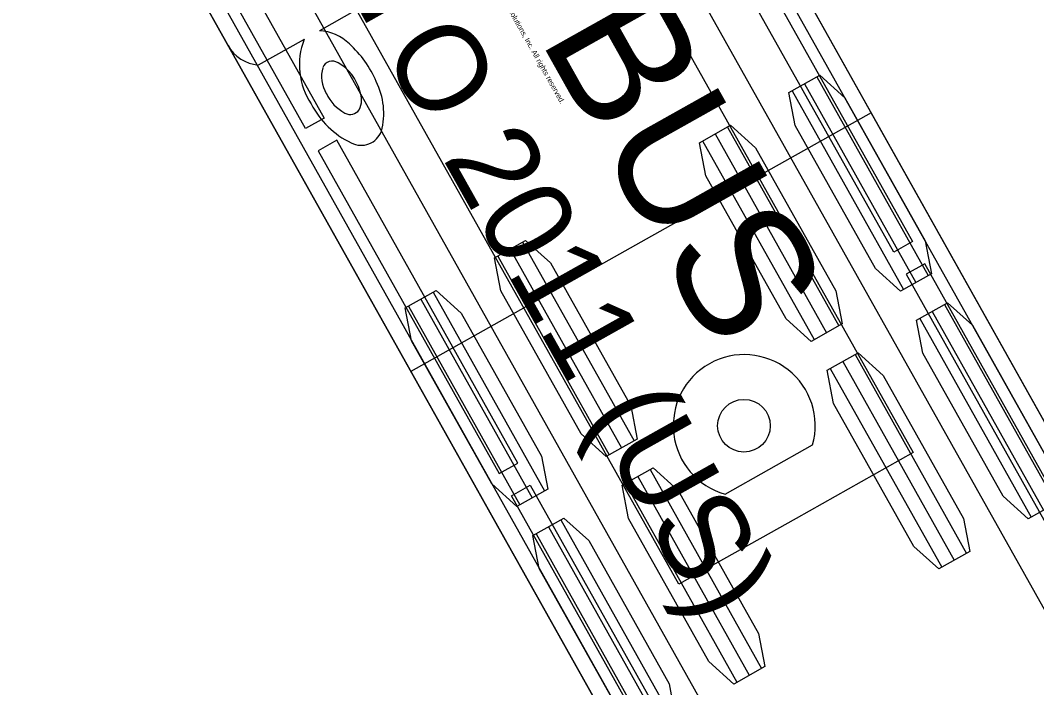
# Model space of a CAD drawing. Extents: x 1639988 to 1641860, y 841974 to 844187.
# Drawn here: x 1640597 to 1640613.36, y 843356.33 to 843367.07 of the extents above; entities that cross this region are included whole.
import ezdxf

# ---------------------------------------------------------------- set-up
doc = ezdxf.new("R2010")
doc.units = 0
for name, color, linetype in [('Scratch_Level_1', 7, 'Continuous'), ('Scratch_Level_2', 7, 'Continuous'), ('Scratch_Level_3', 7, 'Continuous'), ('Scratch_Level_4', 7, 'Continuous'), ('Scratch_Level_5', 7, 'Continuous'), ('Scratch_Level_6', 7, 'Continuous')]:
    doc.layers.add(name, color=color, linetype=linetype)

msp = doc.modelspace()

# ---------------------------------------------------------------- linework, layer by layer
at = {"layer": 'Scratch_Level_1'}
for p, q in [((1640609.821, 843366.155), (1640611.615, 843362.958)), ((1640609.621, 843366.043), (1640611.415, 843362.845)), ((1640609.421, 843365.931), (1640611.215, 843362.733)), ((1640608.382, 843365.348), (1640610.176, 843362.15)), ((1640608.182, 843365.236), (1640609.976, 843362.038)), ((1640607.982, 843365.124), (1640609.776, 843361.926)), ((1640605.082, 843363.497), (1640606.877, 843360.299)), ((1640604.883, 843363.384), (1640606.677, 843360.187)), ((1640604.683, 843363.272), (1640606.477, 843360.075)), ((1640603.643, 843362.689), (1640605.438, 843359.491)), ((1640603.444, 843362.577), (1640605.238, 843359.379)), ((1640603.244, 843362.465), (1640605.038, 843359.267)), ((1640611.676, 843362.38), (1640613.47, 843359.183)), ((1640611.876, 843362.493), (1640613.67, 843359.295)), ((1640611.476, 843362.268), (1640613.271, 843359.071)), ((1640610.237, 843361.573), (1640612.031, 843358.375)), ((1640610.437, 843361.685), (1640612.231, 843358.487)), ((1640610.037, 843361.461), (1640611.832, 843358.263)), ((1640608.343, 843359.442), (1640609.753, 843360.233)), ((1640607.138, 843359.834), (1640608.932, 843356.636)), ((1640606.738, 843359.609), (1640608.532, 843356.412)), ((1640606.938, 843359.722), (1640608.732, 843356.524)), ((1640605.499, 843358.914), (1640607.293, 843355.717)), ((1640605.699, 843359.026), (1640607.493, 843355.829)), ((1640605.299, 843358.802), (1640607.093, 843355.604))]:
    msp.add_line(p, q, dxfattribs=at)
for points in [[(1640569.35, 843442.491), (1640571.641, 843437.743), (1640573.976, 843433.013), (1640576.351, 843428.298), (1640578.765, 843423.598), (1640581.214, 843418.911), (1640583.696, 843414.235), (1640586.206, 843409.569), (1640588.742, 843404.91), (1640593.874, 843395.608), (1640599.062, 843386.314), (1640636.63, 843319.355), (1640629.218, 843315.196), (1640629.14, 843315.333), (1640629.14, 843315.333)], [(1640629.14, 843315.333), (1640571.712, 843417.686), (1640569.11, 843422.364), (1640566.534, 843427.059), (1640563.994, 843431.777), (1640560.226, 843438.882)], [(1640600.34, 843366.66), (1640597.808, 843371.174), (1640597.225, 843370.382), (1640597.224, 843370.382), (1640597.232, 843370.344), (1640597.232, 843370.344), (1640597.232, 843370.343), (1640597.271, 843370.273), (1640597.272, 843370.273), (1640597.584, 843370.429), (1640597.634, 843370.339), (1640597.132, 843369.763), (1640597.131, 843369.763), (1640597.072, 843369.866), (1640597.073, 843369.869), (1640597.234, 843370.232), (1640597.234, 843370.235), (1640597.193, 843370.311)], [(1640606.785, 843369.688), (1640606.186, 843369.352), (1640606.302, 843369.144), (1640611.373, 843360.108), (1640609.485, 843359.048), (1640607.596, 843357.989), (1640602.526, 843367.025), (1640602.409, 843367.233), (1640601.811, 843366.897)], [(1640601.565, 843366.759), (1640600.828, 843366.346)], [(1640636.576, 843319.405), (1640636.595, 843319.416), (1640636.561, 843319.478), (1640633.788, 843324.42), (1640610.695, 843365.576), (1640606.989, 843363.496), (1640603.283, 843361.416), (1640626.375, 843320.261), (1640629.149, 843315.319), (1640629.184, 843315.257), (1640629.203, 843315.268)]]:
    msp.add_lwpolyline(points, dxfattribs=at)
for points in [[(1640609.371, 843365.903), (1640609.87, 843366.183), (1640610.272, 843365.82), (1640611.564, 843363.517), (1640611.665, 843362.985), (1640611.166, 843362.706), (1640610.764, 843363.069), (1640609.472, 843365.371)], [(1640607.933, 843365.096), (1640608.431, 843365.376), (1640608.833, 843365.012), (1640610.125, 843362.71), (1640610.226, 843362.178), (1640609.727, 843361.898), (1640609.325, 843362.261), (1640608.033, 843364.564)], [(1640604.633, 843363.244), (1640605.132, 843363.524), (1640605.533, 843363.161), (1640606.825, 843360.859), (1640606.926, 843360.327), (1640606.427, 843360.047), (1640606.026, 843360.41), (1640604.734, 843362.712)], [(1640603.194, 843362.437), (1640603.693, 843362.717), (1640604.094, 843362.354), (1640605.386, 843360.051), (1640605.487, 843359.519), (1640604.988, 843359.239), (1640604.587, 843359.603), (1640603.295, 843361.905)], [(1640611.427, 843362.24), (1640611.926, 843362.52), (1640612.327, 843362.157), (1640613.619, 843359.855), (1640613.72, 843359.323), (1640613.221, 843359.043), (1640612.819, 843359.406), (1640611.528, 843361.708)], [(1640609.988, 843361.433), (1640610.487, 843361.713), (1640610.888, 843361.35), (1640612.18, 843359.047), (1640612.281, 843358.515), (1640611.782, 843358.235), (1640611.381, 843358.599), (1640610.089, 843360.901)], [(1640606.688, 843359.582), (1640607.187, 843359.862), (1640607.589, 843359.498), (1640608.881, 843357.196), (1640608.981, 843356.664), (1640608.483, 843356.384), (1640608.081, 843356.747), (1640606.789, 843359.05)], [(1640605.249, 843358.774), (1640605.748, 843359.054), (1640606.15, 843358.691), (1640607.442, 843356.388), (1640607.542, 843355.856), (1640607.044, 843355.577), (1640606.642, 843355.94), (1640605.35, 843358.242)]]:
    msp.add_lwpolyline(points, close=True, dxfattribs=at)
msp.add_circle((1640608.647, 843360.541), 0.424, dxfattribs=at)
for centre, radius, start, end in [((1640601.78, 843366.169), 0.729, 45.1057, 87.6197), ((1640600.88, 843366.963), 0.619, 209.2952, 265.1369), ((1640602.625, 843366.351), 1.136, 158.9272, 213.7185), ((1640601.135, 843365.401), 1.73, 23.1239, 47.9224), ((1640602.368, 843366.162), 0.522, 164.3026, 211.4667), ((1640602.021, 843366.24), 0.169, 57.7316, 157.8503), ((1640601.753, 843365.745), 0.732, 14.4711, 60.7055), ((1640601.711, 843365.572), 1.136, 345.0612, 26.5819), ((1640602.529, 843366.162), 0.664, 204.2011, 242.4228), ((1640602.128, 843365.788), 0.362, 333.5938, 22.6348), ((1640602.939, 843366.368), 1.416, 207.2254, 244.2932), ((1640602.308, 843365.721), 0.172, 239.5988, 326.7494), ((1640602.484, 843365.399), 0.346, 242.6899, 339.703), ((1640608.652, 843360.542), 1.143, 344.2972, 254.2972)]:
    msp.add_arc(centre, radius, start, end, dxfattribs=at)
at = {"layer": 'Scratch_Level_2'}
for p, q in [((1640609.821, 843366.155), (1640611.615, 843362.958)), ((1640609.621, 843366.043), (1640611.415, 843362.845)), ((1640609.421, 843365.931), (1640611.215, 843362.733)), ((1640608.382, 843365.348), (1640610.176, 843362.15)), ((1640608.182, 843365.236), (1640609.976, 843362.038)), ((1640607.982, 843365.124), (1640609.776, 843361.926)), ((1640605.082, 843363.497), (1640606.877, 843360.299)), ((1640604.883, 843363.384), (1640606.677, 843360.187)), ((1640604.683, 843363.272), (1640606.477, 843360.075)), ((1640603.643, 843362.689), (1640605.438, 843359.491)), ((1640603.444, 843362.577), (1640605.238, 843359.379)), ((1640603.244, 843362.465), (1640605.038, 843359.267)), ((1640611.676, 843362.38), (1640613.47, 843359.183)), ((1640611.876, 843362.493), (1640613.67, 843359.295)), ((1640611.476, 843362.268), (1640613.271, 843359.071)), ((1640610.237, 843361.573), (1640612.031, 843358.375)), ((1640610.437, 843361.685), (1640612.231, 843358.487)), ((1640610.037, 843361.461), (1640611.832, 843358.263)), ((1640608.343, 843359.442), (1640609.753, 843360.233)), ((1640607.138, 843359.834), (1640608.932, 843356.636)), ((1640606.738, 843359.609), (1640608.532, 843356.412)), ((1640606.938, 843359.722), (1640608.732, 843356.524)), ((1640605.499, 843358.914), (1640607.293, 843355.717)), ((1640605.699, 843359.026), (1640607.493, 843355.829)), ((1640605.299, 843358.802), (1640607.093, 843355.604))]:
    msp.add_line(p, q, dxfattribs=at)
for points in [[(1640569.35, 843442.491), (1640571.641, 843437.743), (1640573.976, 843433.013), (1640576.351, 843428.298), (1640578.765, 843423.598), (1640581.214, 843418.911), (1640583.696, 843414.235), (1640586.206, 843409.569), (1640588.742, 843404.91), (1640593.874, 843395.608), (1640599.062, 843386.314), (1640636.63, 843319.355), (1640629.218, 843315.196), (1640629.144, 843315.327), (1640629.144, 843315.327)], [(1640629.144, 843315.327), (1640571.712, 843417.686), (1640569.11, 843422.364), (1640566.534, 843427.059), (1640563.994, 843431.777), (1640560.226, 843438.882)], [(1640600.34, 843366.66), (1640597.808, 843371.174), (1640597.225, 843370.382), (1640597.224, 843370.382), (1640597.232, 843370.344), (1640597.232, 843370.344), (1640597.232, 843370.343), (1640597.271, 843370.273), (1640597.272, 843370.273), (1640597.584, 843370.429), (1640597.634, 843370.339), (1640597.132, 843369.763), (1640597.131, 843369.763), (1640597.072, 843369.866), (1640597.073, 843369.869), (1640597.234, 843370.232), (1640597.234, 843370.235), (1640597.193, 843370.311)], [(1640606.785, 843369.688), (1640606.186, 843369.352), (1640606.302, 843369.144), (1640611.373, 843360.108), (1640609.485, 843359.048), (1640607.596, 843357.989), (1640602.526, 843367.025), (1640602.409, 843367.233), (1640601.811, 843366.897)], [(1640601.565, 843366.759), (1640600.828, 843366.346)], [(1640636.576, 843319.405), (1640636.595, 843319.416), (1640636.561, 843319.478), (1640633.788, 843324.42), (1640610.695, 843365.576), (1640606.989, 843363.496), (1640603.283, 843361.416), (1640626.375, 843320.261), (1640629.149, 843315.319), (1640629.184, 843315.257), (1640629.203, 843315.268)]]:
    msp.add_lwpolyline(points, dxfattribs=at)
for points in [[(1640609.371, 843365.903), (1640609.87, 843366.183), (1640610.272, 843365.82), (1640611.564, 843363.517), (1640611.665, 843362.985), (1640611.166, 843362.706), (1640610.764, 843363.069), (1640609.472, 843365.371)], [(1640607.933, 843365.096), (1640608.431, 843365.376), (1640608.833, 843365.012), (1640610.125, 843362.71), (1640610.226, 843362.178), (1640609.727, 843361.898), (1640609.325, 843362.261), (1640608.033, 843364.564)], [(1640604.633, 843363.244), (1640605.132, 843363.524), (1640605.533, 843363.161), (1640606.825, 843360.859), (1640606.926, 843360.327), (1640606.427, 843360.047), (1640606.026, 843360.41), (1640604.734, 843362.712)], [(1640603.194, 843362.437), (1640603.693, 843362.717), (1640604.094, 843362.354), (1640605.386, 843360.051), (1640605.487, 843359.519), (1640604.988, 843359.239), (1640604.587, 843359.603), (1640603.295, 843361.905)], [(1640611.427, 843362.24), (1640611.926, 843362.52), (1640612.327, 843362.157), (1640613.619, 843359.855), (1640613.72, 843359.323), (1640613.221, 843359.043), (1640612.819, 843359.406), (1640611.528, 843361.708)], [(1640609.988, 843361.433), (1640610.487, 843361.713), (1640610.888, 843361.35), (1640612.18, 843359.047), (1640612.281, 843358.515), (1640611.782, 843358.235), (1640611.381, 843358.599), (1640610.089, 843360.901)], [(1640606.688, 843359.582), (1640607.187, 843359.862), (1640607.589, 843359.498), (1640608.881, 843357.196), (1640608.981, 843356.664), (1640608.483, 843356.384), (1640608.081, 843356.747), (1640606.789, 843359.05)], [(1640605.249, 843358.774), (1640605.748, 843359.054), (1640606.15, 843358.691), (1640607.442, 843356.388), (1640607.542, 843355.856), (1640607.044, 843355.577), (1640606.642, 843355.94), (1640605.35, 843358.242)]]:
    msp.add_lwpolyline(points, close=True, dxfattribs=at)
msp.add_circle((1640608.647, 843360.541), 0.424, dxfattribs=at)
for centre, radius, start, end in [((1640601.78, 843366.169), 0.729, 45.1057, 87.6197), ((1640600.88, 843366.963), 0.619, 209.2952, 265.1369), ((1640602.625, 843366.351), 1.136, 158.9272, 213.7185), ((1640601.135, 843365.401), 1.73, 23.1239, 47.9224), ((1640602.368, 843366.162), 0.522, 164.3026, 211.4667), ((1640602.021, 843366.24), 0.169, 57.7316, 157.8503), ((1640601.753, 843365.745), 0.732, 14.4711, 60.7055), ((1640601.711, 843365.572), 1.136, 345.0612, 26.5819), ((1640602.529, 843366.162), 0.664, 204.2011, 242.4228), ((1640602.128, 843365.788), 0.362, 333.5938, 22.6348), ((1640602.939, 843366.368), 1.416, 207.2254, 244.2932), ((1640602.308, 843365.721), 0.172, 239.5988, 326.7494), ((1640602.484, 843365.399), 0.346, 242.6899, 339.703), ((1640608.652, 843360.542), 1.143, 344.2972, 254.2972)]:
    msp.add_arc(centre, radius, start, end, dxfattribs=at)
at = {"layer": 'Scratch_Level_3'}
for p, q in [((1640609.821, 843366.155), (1640611.615, 843362.958)), ((1640609.621, 843366.043), (1640611.415, 843362.845)), ((1640609.421, 843365.931), (1640611.215, 843362.733)), ((1640608.382, 843365.348), (1640610.176, 843362.15)), ((1640608.182, 843365.236), (1640609.976, 843362.038)), ((1640607.982, 843365.124), (1640609.776, 843361.926)), ((1640605.082, 843363.497), (1640606.877, 843360.299)), ((1640604.883, 843363.384), (1640606.677, 843360.187)), ((1640604.683, 843363.272), (1640606.477, 843360.075)), ((1640603.643, 843362.689), (1640605.438, 843359.491)), ((1640603.444, 843362.577), (1640605.238, 843359.379)), ((1640603.244, 843362.465), (1640605.038, 843359.267)), ((1640611.676, 843362.38), (1640613.47, 843359.183)), ((1640611.876, 843362.493), (1640613.67, 843359.295)), ((1640611.476, 843362.268), (1640613.271, 843359.071)), ((1640610.237, 843361.573), (1640612.031, 843358.375)), ((1640610.437, 843361.685), (1640612.231, 843358.487)), ((1640610.037, 843361.461), (1640611.832, 843358.263)), ((1640608.343, 843359.442), (1640609.753, 843360.233)), ((1640607.138, 843359.834), (1640608.932, 843356.636)), ((1640606.738, 843359.609), (1640608.532, 843356.412)), ((1640606.938, 843359.722), (1640608.732, 843356.524)), ((1640605.499, 843358.914), (1640607.293, 843355.717)), ((1640605.699, 843359.026), (1640607.493, 843355.829)), ((1640605.299, 843358.802), (1640607.093, 843355.604))]:
    msp.add_line(p, q, dxfattribs=at)
for points in [[(1640569.35, 843442.491), (1640571.641, 843437.743), (1640573.976, 843433.013), (1640576.351, 843428.298), (1640578.765, 843423.598), (1640581.214, 843418.911), (1640583.696, 843414.235), (1640586.206, 843409.569), (1640588.742, 843404.91), (1640593.874, 843395.608), (1640599.062, 843386.314), (1640636.63, 843319.355), (1640629.218, 843315.196), (1640629.149, 843315.318), (1640629.149, 843315.318)], [(1640629.149, 843315.318), (1640571.712, 843417.686), (1640569.11, 843422.364), (1640566.534, 843427.059), (1640563.994, 843431.777), (1640560.226, 843438.882)], [(1640600.34, 843366.66), (1640597.808, 843371.174), (1640597.225, 843370.382), (1640597.224, 843370.382), (1640597.232, 843370.344), (1640597.232, 843370.344), (1640597.232, 843370.343), (1640597.271, 843370.273), (1640597.272, 843370.273), (1640597.584, 843370.429), (1640597.634, 843370.339), (1640597.132, 843369.763), (1640597.131, 843369.763), (1640597.072, 843369.866), (1640597.073, 843369.869), (1640597.234, 843370.232), (1640597.234, 843370.235), (1640597.193, 843370.311)], [(1640606.785, 843369.688), (1640606.186, 843369.352), (1640606.302, 843369.144), (1640611.373, 843360.108), (1640609.485, 843359.048), (1640607.596, 843357.989), (1640602.526, 843367.025), (1640602.409, 843367.233), (1640601.811, 843366.897)], [(1640601.565, 843366.759), (1640600.828, 843366.346)], [(1640636.576, 843319.405), (1640636.595, 843319.416), (1640636.561, 843319.478), (1640633.788, 843324.42), (1640610.695, 843365.576), (1640606.989, 843363.496), (1640603.283, 843361.416), (1640626.375, 843320.261), (1640629.149, 843315.319), (1640629.184, 843315.257), (1640629.203, 843315.268)]]:
    msp.add_lwpolyline(points, dxfattribs=at)
for points in [[(1640609.371, 843365.903), (1640609.87, 843366.183), (1640610.272, 843365.82), (1640611.564, 843363.517), (1640611.665, 843362.985), (1640611.166, 843362.706), (1640610.764, 843363.069), (1640609.472, 843365.371)], [(1640607.933, 843365.096), (1640608.431, 843365.376), (1640608.833, 843365.012), (1640610.125, 843362.71), (1640610.226, 843362.178), (1640609.727, 843361.898), (1640609.325, 843362.261), (1640608.033, 843364.564)], [(1640604.633, 843363.244), (1640605.132, 843363.524), (1640605.533, 843363.161), (1640606.825, 843360.859), (1640606.926, 843360.327), (1640606.427, 843360.047), (1640606.026, 843360.41), (1640604.734, 843362.712)], [(1640603.194, 843362.437), (1640603.693, 843362.717), (1640604.094, 843362.354), (1640605.386, 843360.051), (1640605.487, 843359.519), (1640604.988, 843359.239), (1640604.587, 843359.603), (1640603.295, 843361.905)], [(1640611.427, 843362.24), (1640611.926, 843362.52), (1640612.327, 843362.157), (1640613.619, 843359.855), (1640613.72, 843359.323), (1640613.221, 843359.043), (1640612.819, 843359.406), (1640611.528, 843361.708)], [(1640609.988, 843361.433), (1640610.487, 843361.713), (1640610.888, 843361.35), (1640612.18, 843359.047), (1640612.281, 843358.515), (1640611.782, 843358.235), (1640611.381, 843358.599), (1640610.089, 843360.901)], [(1640606.688, 843359.582), (1640607.187, 843359.862), (1640607.589, 843359.498), (1640608.881, 843357.196), (1640608.981, 843356.664), (1640608.483, 843356.384), (1640608.081, 843356.747), (1640606.789, 843359.05)], [(1640605.249, 843358.774), (1640605.748, 843359.054), (1640606.15, 843358.691), (1640607.442, 843356.388), (1640607.542, 843355.856), (1640607.044, 843355.577), (1640606.642, 843355.94), (1640605.35, 843358.242)]]:
    msp.add_lwpolyline(points, close=True, dxfattribs=at)
msp.add_circle((1640608.647, 843360.541), 0.424, dxfattribs=at)
for centre, radius, start, end in [((1640601.78, 843366.169), 0.729, 45.1057, 87.6197), ((1640600.88, 843366.963), 0.619, 209.2952, 265.1369), ((1640602.625, 843366.351), 1.136, 158.9272, 213.7185), ((1640601.135, 843365.401), 1.73, 23.1239, 47.9224), ((1640602.368, 843366.162), 0.522, 164.3026, 211.4667), ((1640602.021, 843366.24), 0.169, 57.7316, 157.8503), ((1640601.753, 843365.745), 0.732, 14.4711, 60.7055), ((1640601.711, 843365.572), 1.136, 345.0612, 26.5819), ((1640602.529, 843366.162), 0.664, 204.2011, 242.4228), ((1640602.128, 843365.788), 0.362, 333.5938, 22.6348), ((1640602.939, 843366.368), 1.416, 207.2254, 244.2932), ((1640602.308, 843365.721), 0.172, 239.5988, 326.7494), ((1640602.484, 843365.399), 0.346, 242.6899, 339.703), ((1640608.652, 843360.542), 1.143, 344.2972, 254.2972)]:
    msp.add_arc(centre, radius, start, end, dxfattribs=at)
at = {"layer": 'Scratch_Level_4'}
for p, q in [((1640616.744, 843351.77), (1640598.916, 843383.542)), ((1640594.087, 843380.832), (1640611.914, 843349.06))]:
    msp.add_line(p, q, dxfattribs=at)
for points in [[(1640611.208, 843347.292), (1640590.328, 843384.504), (1640574.652, 843412.392), (1640569.434, 843421.74), (1640561.561, 843435.788), (1640560.271, 843438.147), (1640559.001, 843440.517)], [(1640569.265, 843440.462), (1640571.686, 843435.764), (1640574.153, 843431.085), (1640576.662, 843426.421), (1640579.206, 843421.768), (1640584.378, 843412.479), (1640618.769, 843351.186), (1640611.357, 843347.027), (1640611.208, 843347.292), (1640611.208, 843347.292)], [(1640617.816, 843352.371), (1640615.562, 843356.389), (1640615.711, 843356.637), (1640613.998, 843359.689), (1640613.709, 843359.691), (1640603.407, 843378.051), (1640603.478, 843378.439), (1640601.765, 843381.491), (1640601.397, 843381.633)], [(1640593.014, 843380.23), (1640594.423, 843377.72), (1640594.352, 843377.332), (1640596.065, 843374.28), (1640596.433, 843374.138), (1640606.735, 843355.778), (1640606.586, 843355.53), (1640608.298, 843352.477), (1640608.587, 843352.475), (1640610.842, 843348.458)]]:
    msp.add_lwpolyline(points, dxfattribs=at)
for points in [[(1640601.889, 843365.493), (1640601.588, 843365.324), (1640598.672, 843370.522), (1640598.973, 843370.69)], [(1640608.143, 843368.532), (1640608.444, 843368.701), (1640611.359, 843363.504), (1640611.059, 843363.335)], [(1640602.09, 843365.136), (1640601.789, 843364.967), (1640604.705, 843359.77), (1640605.005, 843359.939)], [(1640614.175, 843357.782), (1640614.476, 843357.95), (1640611.559, 843363.148), (1640611.259, 843362.978)], [(1640608.122, 843354.385), (1640607.821, 843354.216), (1640604.905, 843359.414), (1640605.206, 843359.582)]]:
    msp.add_lwpolyline(points, close=True, dxfattribs=at)
at = {"layer": 'Scratch_Level_5'}
for p, q in [((1640616.744, 843351.77), (1640598.916, 843383.542)), ((1640594.087, 843380.832), (1640611.914, 843349.06))]:
    msp.add_line(p, q, dxfattribs=at)
for points in [[(1640611.214, 843347.281), (1640590.328, 843384.504), (1640574.652, 843412.392), (1640569.434, 843421.74), (1640561.561, 843435.788), (1640560.271, 843438.147), (1640559.001, 843440.517)], [(1640569.265, 843440.462), (1640571.686, 843435.764), (1640574.153, 843431.085), (1640576.662, 843426.421), (1640579.206, 843421.768), (1640584.378, 843412.479), (1640618.769, 843351.186), (1640611.357, 843347.027), (1640611.214, 843347.281), (1640611.214, 843347.281)], [(1640617.816, 843352.371), (1640615.562, 843356.389), (1640615.711, 843356.637), (1640613.998, 843359.689), (1640613.709, 843359.691), (1640603.407, 843378.051), (1640603.478, 843378.439), (1640601.765, 843381.491), (1640601.397, 843381.633)], [(1640593.014, 843380.23), (1640594.423, 843377.72), (1640594.352, 843377.332), (1640596.065, 843374.28), (1640596.433, 843374.138), (1640606.735, 843355.778), (1640606.586, 843355.53), (1640608.298, 843352.477), (1640608.587, 843352.475), (1640610.842, 843348.458)]]:
    msp.add_lwpolyline(points, dxfattribs=at)
for points in [[(1640601.889, 843365.493), (1640601.588, 843365.324), (1640598.672, 843370.522), (1640598.973, 843370.69)], [(1640608.143, 843368.532), (1640608.444, 843368.701), (1640611.359, 843363.504), (1640611.059, 843363.335)], [(1640602.09, 843365.136), (1640601.789, 843364.967), (1640604.705, 843359.77), (1640605.005, 843359.939)], [(1640614.175, 843357.782), (1640614.476, 843357.95), (1640611.559, 843363.148), (1640611.259, 843362.978)], [(1640608.122, 843354.385), (1640607.821, 843354.216), (1640604.905, 843359.414), (1640605.206, 843359.582)]]:
    msp.add_lwpolyline(points, close=True, dxfattribs=at)
at = {"layer": 'Scratch_Level_6'}
for p, q in [((1640616.744, 843351.77), (1640598.916, 843383.542)), ((1640594.087, 843380.832), (1640611.914, 843349.06))]:
    msp.add_line(p, q, dxfattribs=at)
for points in [[(1640611.238, 843347.239), (1640590.328, 843384.504), (1640574.652, 843412.392), (1640569.434, 843421.74), (1640561.561, 843435.788), (1640560.271, 843438.147), (1640559.001, 843440.517)], [(1640569.265, 843440.462), (1640571.686, 843435.764), (1640574.153, 843431.085), (1640576.662, 843426.421), (1640579.206, 843421.768), (1640584.378, 843412.479), (1640618.769, 843351.186), (1640611.357, 843347.027), (1640611.238, 843347.239), (1640611.238, 843347.239)], [(1640617.816, 843352.371), (1640615.562, 843356.389), (1640615.711, 843356.637), (1640613.998, 843359.689), (1640613.709, 843359.691), (1640603.407, 843378.051), (1640603.478, 843378.439), (1640601.765, 843381.491), (1640601.397, 843381.633)], [(1640593.014, 843380.23), (1640594.423, 843377.72), (1640594.352, 843377.332), (1640596.065, 843374.28), (1640596.433, 843374.138), (1640606.735, 843355.778), (1640606.586, 843355.53), (1640608.298, 843352.477), (1640608.587, 843352.475), (1640610.842, 843348.458)]]:
    msp.add_lwpolyline(points, dxfattribs=at)
for points in [[(1640601.889, 843365.493), (1640601.588, 843365.324), (1640598.672, 843370.522), (1640598.973, 843370.69)], [(1640608.143, 843368.532), (1640608.444, 843368.701), (1640611.359, 843363.504), (1640611.059, 843363.335)], [(1640602.09, 843365.136), (1640601.789, 843364.967), (1640604.705, 843359.77), (1640605.005, 843359.939)], [(1640614.175, 843357.782), (1640614.476, 843357.95), (1640611.559, 843363.148), (1640611.259, 843362.978)], [(1640608.122, 843354.385), (1640607.821, 843354.216), (1640604.905, 843359.414), (1640605.206, 843359.582)]]:
    msp.add_lwpolyline(points, close=True, dxfattribs=at)

# ---------------------------------------------------------------- texts
at = {"layer": 'Scratch_Level_4'}
for s, height, p in [('CITY-BUS', 2.125, (1640601.711, 843373.25)), ('AASHTO 2011 (US)', 1.41667, (1640599.716, 843372.102)), ('(c) 2019 Transoft Solutions, Inc. All rights reserved.', 0.085, (1640604.391, 843368.038))]:
    msp.add_text(s, height=height, rotation=299.2972, dxfattribs=at).set_placement(p)
at = {"layer": 'Scratch_Level_5'}
for s, height, p in [('CITY-BUS', 2.125, (1640601.711, 843373.25)), ('AASHTO 2011 (US)', 1.41667, (1640599.716, 843372.102)), ('(c) 2019 Transoft Solutions, Inc. All rights reserved.', 0.085, (1640604.391, 843368.038))]:
    msp.add_text(s, height=height, rotation=299.2972, dxfattribs=at).set_placement(p)
at = {"layer": 'Scratch_Level_6'}
for s, height, p in [('CITY-BUS', 2.125, (1640601.711, 843373.25)), ('AASHTO 2011 (US)', 1.41667, (1640599.716, 843372.102)), ('(c) 2019 Transoft Solutions, Inc. All rights reserved.', 0.085, (1640604.391, 843368.038))]:
    msp.add_text(s, height=height, rotation=299.2972, dxfattribs=at).set_placement(p)

doc.saveas('drawing.dxf')
